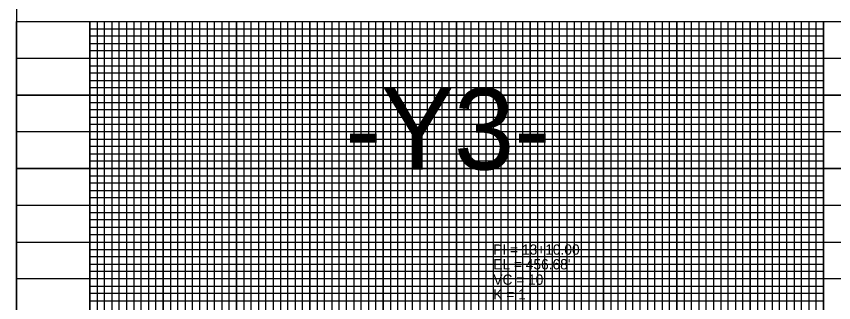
# Model space of a CAD drawing. Extents: x 571503 to 593215, y -77195 to -51828.
# Drawn here: x 585926 to 586483, y -53362 to -53168 of the extents above; entities that cross this region are included whole.
import ezdxf

# ---------------------------------------------------------------- set-up
doc = ezdxf.new("R2010")
doc.units = 0
for name, color, linetype in [('Default', 7, 'Continuous'), ('Prop VPI Label', 7, 'Continuous'), ('Sheet Clip Boundary CELL', 7, 'Continuous'), ('Sheet DOT Grid CELL', 7, 'Continuous'), ('Sheet Profile CELL', 7, 'Continuous'), ('Sheet Profile Grid Major CELL', 7, 'Continuous'), ('Sheet Profile Grid Middle CELL', 7, 'Continuous'), ('Sheet Profile Grid Minor CELL', 7, 'Continuous')]:
    doc.layers.add(name, color=color, linetype=linetype)

msp = doc.modelspace()

# ---------------------------------------------------------------- linework, layer by layer
at = {"layer": 'Sheet Clip Boundary CELL'}
msp.add_lwpolyline([(585975.93, -53171.12), (587375.93, -53171.12), (587375.93, -53671.12), (585975.93, -53671.12)], close=True, dxfattribs=at)
at = {"layer": 'Sheet DOT Grid CELL'}
for p, q in [((585925.93, -53671.12), (585925.93, -53171.12)), ((585925.93, -53171.12), (587425.82, -53171.12)), ((585975.93, -53671.12), (585975.93, -53171.12)), ((585975.93, -53171.12), (585975.93, -53671.12)), ((586025.93, -53671.12), (586025.93, -53171.12)), ((586025.93, -53171.12), (586025.93, -53671.12)), ((586075.93, -53671.12), (586075.93, -53171.12)), ((586075.93, -53171.12), (586075.93, -53671.12)), ((586125.93, -53671.12), (586125.93, -53171.12)), ((586125.93, -53171.12), (586125.93, -53671.12)), ((586175.93, -53671.12), (586175.93, -53171.12)), ((586175.93, -53171.12), (586175.93, -53671.12)), ((586225.93, -53671.12), (586225.93, -53171.12)), ((586225.93, -53171.12), (586225.93, -53671.12)), ((586275.93, -53671.12), (586275.93, -53171.12)), ((586275.93, -53171.12), (586275.93, -53671.12)), ((586325.93, -53671.12), (586325.93, -53171.12)), ((586325.93, -53171.12), (586325.93, -53671.12)), ((586375.93, -53671.12), (586375.93, -53171.12)), ((586375.93, -53171.12), (586375.93, -53671.12)), ((586425.93, -53671.12), (586425.93, -53171.12)), ((586425.93, -53171.12), (586425.93, -53671.12)), ((586475.93, -53671.12), (586475.93, -53171.12)), ((586475.93, -53171.12), (586475.93, -53671.12)), ((585925.93, -53221.12), (587425.93, -53221.12)), ((585925.93, -53221.12), (587425.82, -53221.12)), ((585925.93, -53271.12), (587425.93, -53271.12)), ((585925.93, -53271.12), (587425.82, -53271.12)), ((585925.93, -53321.12), (587425.93, -53321.12)), ((585925.93, -53321.12), (587425.82, -53321.12))]:
    msp.add_line(p, q, dxfattribs=at)
at = {"layer": 'Sheet Profile CELL'}
msp.add_line((585925.93, -53171.12), (587425.93, -53171.12), dxfattribs=at)
msp.add_lwpolyline([(587425.93, -52646.12), (585925.93, -52646.12), (585925.93, -53696.12), (587425.93, -53696.12)], close=True, dxfattribs=at)
at = {"layer": 'Sheet Profile Grid Major CELL'}
msp.add_line((586425.93, -53171.12), (586475.93, -53171.12), dxfattribs=at)
for points in [[(585975.93, -53171.12), (585975.93, -53671.12), (586025.93, -53671.12), (586025.93, -53171.12), (586075.93, -53171.12), (586075.93, -53671.12), (586125.93, -53671.12), (586125.93, -53171.12), (586175.93, -53171.12), (586175.93, -53671.12), (586225.93, -53671.12), (586225.93, -53171.12), (586275.93, -53171.12), (586275.93, -53671.12), (586325.93, -53671.12), (586325.93, -53171.12), (586375.93, -53171.12), (586375.93, -53671.12), (586425.93, -53671.12), (586425.93, -53171.12), (586475.93, -53171.12), (586475.93, -53671.12), (586525.93, -53671.12)], [(587425.93, -53221.12), (585925.93, -53221.12)], [(587425.93, -53271.12), (585925.93, -53271.12), (585925.93, -53321.12), (587425.93, -53321.12)]]:
    msp.add_lwpolyline(points, dxfattribs=at)
at = {"layer": 'Sheet Profile Grid Middle CELL'}
for p, q in [((585950.93, -53171.12), (586000.93, -53171.12)), ((586000.93, -53171.12), (586000.93, -53671.12)), ((586050.93, -53671.12), (586050.93, -53171.12)), ((586050.93, -53171.12), (586100.93, -53171.12)), ((586100.93, -53171.12), (586100.93, -53671.12)), ((586150.93, -53671.12), (586150.93, -53171.12)), ((586150.93, -53171.12), (586200.93, -53171.12)), ((586200.93, -53171.12), (586200.93, -53671.12)), ((586250.93, -53671.12), (586250.93, -53171.12)), ((586250.93, -53171.12), (586300.93, -53171.12)), ((586300.93, -53171.12), (586300.93, -53671.12)), ((586350.93, -53671.12), (586350.93, -53171.12)), ((586350.93, -53171.12), (586400.93, -53171.12)), ((586400.93, -53171.12), (586400.93, -53671.12)), ((586450.93, -53671.12), (586450.93, -53171.12)), ((586450.93, -53171.12), (586500.93, -53171.12))]:
    msp.add_line(p, q, dxfattribs=at)
for points in [[(585925.93, -53196.12), (587425.93, -53196.12)], [(587375.93, -53246.12), (585925.93, -53246.12), (585925.93, -53296.12), (587425.93, -53296.12)], [(587425.93, -53346.12), (585925.93, -53346.12), (585925.93, -53396.12), (587425.93, -53396.12)]]:
    msp.add_lwpolyline(points, dxfattribs=at)
at = {"layer": 'Sheet Profile Grid Minor CELL'}
for p, q in [((585975.93, -53176.12), (586475.93, -53176.12)), ((586475.93, -53181.12), (585975.93, -53181.12)), ((585975.93, -53186.12), (586475.93, -53186.12)), ((586475.93, -53191.12), (585975.93, -53191.12)), ((585975.93, -53201.12), (586475.93, -53201.12)), ((586475.93, -53206.12), (585975.93, -53206.12)), ((585975.93, -53211.12), (586475.93, -53211.12)), ((586475.93, -53216.12), (585975.93, -53216.12)), ((585975.93, -53226.12), (586475.93, -53226.12)), ((586475.93, -53231.12), (585975.93, -53231.12)), ((585975.93, -53236.12), (586475.93, -53236.12)), ((586475.93, -53241.12), (585975.93, -53241.12)), ((585975.93, -53251.12), (586475.93, -53251.12)), ((586475.93, -53256.12), (585975.93, -53256.12)), ((585975.93, -53261.12), (586475.93, -53261.12)), ((586475.93, -53266.12), (585975.93, -53266.12)), ((585975.93, -53276.12), (586475.93, -53276.12)), ((586475.93, -53281.12), (585975.93, -53281.12)), ((585975.93, -53286.12), (586475.93, -53286.12)), ((586475.93, -53291.12), (585975.93, -53291.12)), ((585975.93, -53301.12), (586475.93, -53301.12)), ((586475.93, -53306.12), (585975.93, -53306.12)), ((585975.93, -53311.12), (586475.93, -53311.12)), ((586475.93, -53316.12), (585975.93, -53316.12)), ((585975.93, -53326.12), (586475.93, -53326.12)), ((586475.93, -53331.12), (585975.93, -53331.12)), ((585975.93, -53336.12), (586475.93, -53336.12)), ((586475.93, -53341.12), (585975.93, -53341.12)), ((585975.93, -53351.12), (586475.93, -53351.12)), ((586475.93, -53356.12), (585975.93, -53356.12)), ((585975.93, -53361.12), (586475.93, -53361.12))]:
    msp.add_line(p, q, dxfattribs=at)
for points in [[(585975.93, -53171.12), (585980.93, -53171.12), (585980.93, -53671.12)], [(585985.93, -53671.12), (585985.93, -53171.12), (585990.93, -53171.12), (585990.93, -53671.12)], [(585995.93, -53671.12), (585995.93, -53171.12), (586005.93, -53171.12), (586005.93, -53671.12)], [(586010.93, -53671.12), (586010.93, -53171.12), (586015.93, -53171.12), (586015.93, -53671.12)], [(586020.93, -53671.12), (586020.93, -53171.12), (586030.93, -53171.12), (586030.93, -53671.12)], [(586035.93, -53671.12), (586035.93, -53171.12), (586040.93, -53171.12), (586040.93, -53671.12)], [(586045.93, -53671.12), (586045.93, -53171.12), (586055.93, -53171.12), (586055.93, -53671.12)], [(586060.93, -53671.12), (586060.93, -53171.12), (586065.93, -53171.12), (586065.93, -53671.12)], [(586070.93, -53671.12), (586070.93, -53171.12), (586080.93, -53171.12), (586080.93, -53671.12)], [(586085.93, -53671.12), (586085.93, -53171.12), (586090.93, -53171.12), (586090.93, -53671.12)], [(586095.93, -53671.12), (586095.93, -53171.12), (586105.93, -53171.12), (586105.93, -53671.12)], [(586110.93, -53671.12), (586110.93, -53171.12), (586115.93, -53171.12), (586115.93, -53671.12)], [(586120.93, -53671.12), (586120.93, -53171.12), (586130.93, -53171.12), (586130.93, -53671.12)], [(586135.93, -53671.12), (586135.93, -53171.12), (586140.93, -53171.12), (586140.93, -53671.12)], [(586145.93, -53671.12), (586145.93, -53171.12), (586155.93, -53171.12), (586155.93, -53671.12)], [(586160.93, -53671.12), (586160.93, -53171.12), (586165.93, -53171.12), (586165.93, -53671.12)], [(586170.93, -53671.12), (586170.93, -53171.12), (586180.93, -53171.12), (586180.93, -53671.12)], [(586185.93, -53671.12), (586185.93, -53171.12), (586190.93, -53171.12), (586190.93, -53671.12)], [(586195.93, -53671.12), (586195.93, -53171.12), (586205.93, -53171.12), (586205.93, -53671.12)], [(586210.93, -53671.12), (586210.93, -53171.12), (586215.93, -53171.12), (586215.93, -53671.12)], [(586220.93, -53671.12), (586220.93, -53171.12), (586230.93, -53171.12), (586230.93, -53671.12)], [(586235.93, -53671.12), (586235.93, -53171.12), (586240.93, -53171.12), (586240.93, -53671.12)], [(586245.93, -53671.12), (586245.93, -53171.12), (586255.93, -53171.12), (586255.93, -53671.12)], [(586260.93, -53671.12), (586260.93, -53171.12), (586265.93, -53171.12), (586265.93, -53671.12)], [(586270.93, -53671.12), (586270.93, -53171.12), (586280.93, -53171.12), (586280.93, -53671.12)], [(586285.93, -53671.12), (586285.93, -53171.12), (586290.93, -53171.12), (586290.93, -53671.12)], [(586295.93, -53671.12), (586295.93, -53171.12), (586305.93, -53171.12), (586305.93, -53671.12)], [(586310.93, -53671.12), (586310.93, -53171.12), (586315.93, -53171.12), (586315.93, -53671.12)], [(586320.93, -53671.12), (586320.93, -53171.12), (586330.93, -53171.12), (586330.93, -53671.12)], [(586335.93, -53671.12), (586335.93, -53171.12), (586340.93, -53171.12), (586340.93, -53671.12)], [(586345.93, -53671.12), (586345.93, -53171.12), (586355.93, -53171.12), (586355.93, -53671.12)], [(586360.93, -53671.12), (586360.93, -53171.12), (586365.93, -53171.12), (586365.93, -53671.12)], [(586370.93, -53671.12), (586370.93, -53171.12), (586380.93, -53171.12), (586380.93, -53671.12)], [(586385.93, -53671.12), (586385.93, -53171.12), (586390.93, -53171.12), (586390.93, -53671.12)], [(586395.93, -53671.12), (586395.93, -53171.12), (586405.93, -53171.12), (586405.93, -53671.12)], [(586410.93, -53671.12), (586410.93, -53171.12), (586415.93, -53171.12), (586415.93, -53671.12)], [(586420.93, -53671.12), (586420.93, -53171.12), (586430.93, -53171.12), (586430.93, -53671.12)], [(586435.93, -53671.12), (586435.93, -53171.12), (586440.93, -53171.12), (586440.93, -53671.12)], [(586445.93, -53671.12), (586445.93, -53171.12), (586455.93, -53171.12), (586455.93, -53671.12)], [(586460.93, -53671.12), (586460.93, -53171.12), (586465.93, -53171.12), (586465.93, -53671.12)], [(586470.93, -53671.12), (586470.93, -53171.12), (586475.93, -53171.12)]]:
    msp.add_lwpolyline(points, dxfattribs=at)

# ---------------------------------------------------------------- texts
at = {"layer": 'Default'}
msp.add_text('-Y3-', height=55.361, dxfattribs=at).set_placement((586150.02, -53271.83))
at = {"layer": 'Prop VPI Label'}
for s, p in [('PI = 13+10.00', (586250.93, -53329.75)), ("EL = 456.68'", (586250.93, -53339.75)), ("VC = 10'", (586250.93, -53350.21)), ('K = 1', (586250.93, -53360.21))]:
    msp.add_text(s, height=7, dxfattribs=at).set_placement(p)

doc.saveas('drawing.dxf')
